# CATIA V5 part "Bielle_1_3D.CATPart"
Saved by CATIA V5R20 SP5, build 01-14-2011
Part number: Bielle_1_3D
Bounding box of the stored display mesh (mm): x 0 to 155, y -49.989 to 49.989, z -950 to 50
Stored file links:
  J:\Thinkmotion\Projet IAO\A envoyer\Bielle_1_3D.CATPart
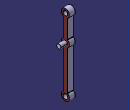
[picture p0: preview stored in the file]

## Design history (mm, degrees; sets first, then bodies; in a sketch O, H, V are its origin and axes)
Body1 (main body)
  Point1 "A": stored without definition
  Line1 to Line3: stored without definition
  Sketch1 on yz-plane, origin (0, 0, 0), H (0, 1, 0), V (0, 0, 1)
    point P1 (-25, -43.3013)
    point P3 (25, -856.6987)
    point P4 (0, -900)
    point P5 (0, 0)
    circle A1 centre (0, 0) radius 30
    arc A2 centre (0, -900) radius 50 from (-25, -856.6987) to (25, -856.6987) ccw
    point P6 (0, -900)
    point P7 (25, -856.6987)
    point P8 (0, 0)
    arc A3 centre (0, 0) radius 50 from (25, -43.3013) to (-25, -43.3013) ccw
    point P9 (25, -43.3013)
    reference projected point E1 (0, 0) from Point1
    arc A4 centre (0, -320) radius 50 from (25, -363.3013) to (25, -276.6987) ccw
    point P10 (0, -320)
    point P12 (25, -363.3013)
    arc A5 centre (0, -320) radius 50 from (-25, -276.6987) to (-25, -363.3013) ccw
    point P13 (-25, -363.3013)
    line L1 (-25, -363.3013) -> (-25, -856.6987)
    reference projected line E2 (0, 0) -> (0, -600) from Line1
    line L2 (25, -363.3013) -> (25, -856.6987)
    point P15 (25, -363.3013)
    line L3 (-25, -43.3013) -> (-25, -276.6987)
    point P16 (-25, -43.3013)
    line L4 (25, -276.6987) -> (25, -43.3013)
    point P17 (25, -43.3013)
    circle A6 centre (0, -900) radius 30
    reference projected point E3 (0, -320) from Line2
    reference projected point E4 (0, -900) from Line3
    radius A2 = 50
    radius A1 = 30
    radius A3 = 50
    radius A4 = 50
    distance L1 E2 = 25
    distance L2 L1 = 50
    radius A6 = 30
    coincidence: P5 V, P8 V, P5 P8, P8 E1, P10 V, P13 A4, P15 A4, P16 A3, P17 A3, L2 L4, L1 L3, P1 P16, P9 P17, P12 P15, P10 E3, P7 P3, P4 P6
    vertical: L2 V, L3 V
    concentricity: A2 E4
  Pad1: profile Sketch1, direction (1, 0, 0), length 72
  Line4: stored without definition
  Sketch2 on end face of Pad1, origin (72, 0, 0), H (0, 1, 0), V (0, 0, 1)
    circle A1 centre (0, -320) radius 25
    point P1 (0, -320)
    reference projected point E1 (0, -320) from Line4
    radius A1 = 25
    coincidence: P1 V, P1 E1
  Pad2: profile Sketch2, direction (1, 0, 0), length 83
  Fillet1: radius 5, on edge [face of Pad1 from Sketch1.A5 | face of Pad1 from Sketch1.L3]; edge [face of Pad1 from Sketch1.L1 | face of Pad1 from Sketch1.A5]; edge [face of Pad1 from Sketch1.A2 | face of Pad1 from Sketch1.L1]; edge [face of Pad1 from Sketch1.L2 | face of Pad1 from Sketch1.A2]; edge [face of Pad1 from Sketch1.A4 | face of Pad1 from Sketch1.L2]; edge [face of Pad1 from Sketch1.L4 | face of Pad1 from Sketch1.A4]; edge [face of Pad1 from Sketch1.A3 | face of Pad1 from Sketch1.L4]; edge [face of Pad1 from Sketch1.L3 | face of Pad1 from Sketch1.A3]
  Chamfer1: length 1, angle 45, on edge [face of Pad2 from Sketch2.A1 | end face of Pad2]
